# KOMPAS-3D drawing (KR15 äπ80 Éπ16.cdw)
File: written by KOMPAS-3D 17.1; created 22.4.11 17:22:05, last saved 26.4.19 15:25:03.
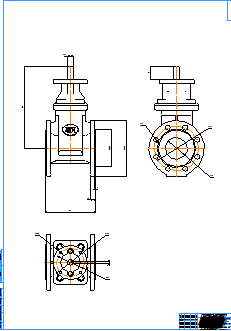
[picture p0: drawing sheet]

Title block, sheet 1: name: KR15 Ду80 Ру16; material: Сталь 20  ГОСТ 1050-2013; mass: 18; sheets: 1; organisation: ООО "Торговый дом АДЛ"; sheet format: A0; stored path: \\adlc.lan\data\АДЛ_ПКД\3D-модели\ADL production\Клиновые задвижки серии KR ГРАНАР\Клиновые задвижки KR15\С голым штоком\KOMPAS 2D\KR15 Ду80 Ру16.cdw

Views: Спереди 7, Проекционный вид 8, Проекционный вид 9
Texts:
  Рама для чертежей
  Лит-Масса-Масштаб
  Материал-Предприятие
  Масштаб
  Изм.
  Лист
  № докум.
  Подп.
  Дата
  Лит.
  Разраб.
  Пров.
  Т.контр.
  Листов
  Внимание! Данный продукт является объектом авторского права ООО «Торговый Дом АДЛ».
  Запрещается изменение, копирование, распространение
  (в том числе путем копирования на другие сайты и ресурсы в Интернете)
  или любое иное использование информации и объектов без предварительного
  согласия правообладателя (ООО «Торговый Дом АДЛ»).
  Н.контр.
  Утв.
  Изменение
  Номер документа
  Подпись
  Обозначение документа
  Наименование изделия
  Масса изделия по ГОСТ 2.109-73
  Порядковый номер листа
  Общее количество листов в документе
  Характер работы, выполненной лицом, подписавшим документ
  Наименование или индекс предприятия, выпускающего документ
  Инв. № подл.
  Подп. и дата
  Взам. инв. №
  Инв. № дубл.
  Инвентарный номер подлинника по ГОСТ 2.501-68
  Подпись принявшего подлинник в отдел технической документации
  Инвентарный номер подлинника, взамен которого выпущен данный подлинник
  Инвентарный номер дубликата по ГОСТ 2.502-68
  Подпись принявшего дубликат в отдел технической документации
  Справ. №
  Перв. примен.
  Обозначение документа, взамен или на основании которого выпущен данный документ
  Обозначение документа, в котором впервые записан данный документ
  Подпись лица, копировавшего чертеж
  Обозначение формата листа
  !Рама для чертежа
Dimensions and other numbers on the sheet: 200; 133; 180; 3; 19; 293; 20; 10; 125; 102; 6; 160; 8 отв.; 80; 45; 1:1; 1; 18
